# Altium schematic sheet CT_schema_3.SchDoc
size 276 x 169 mm
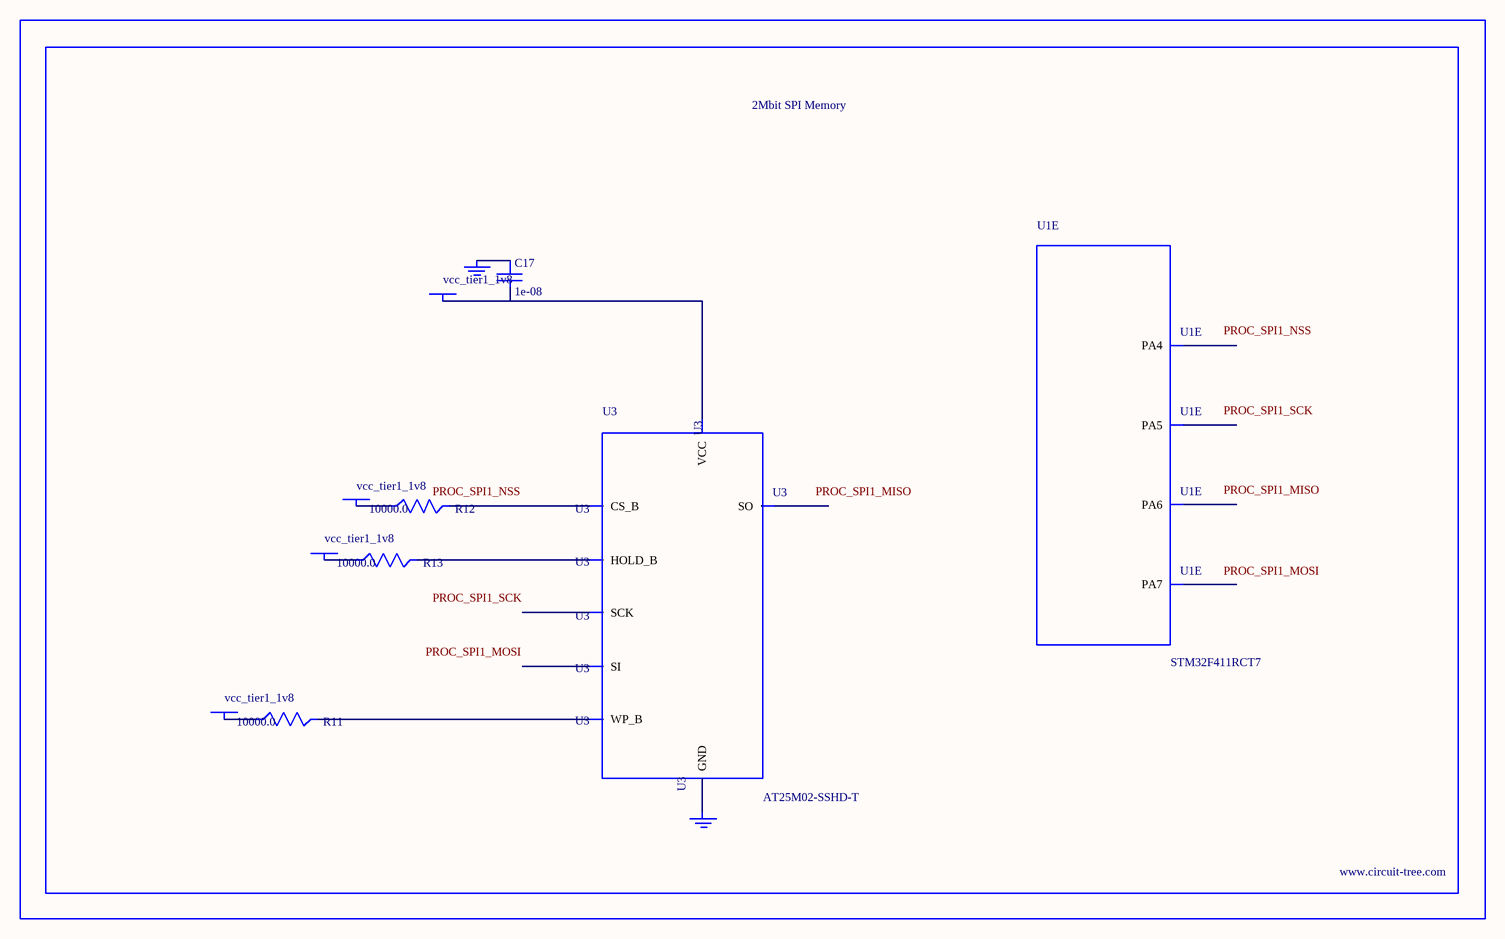
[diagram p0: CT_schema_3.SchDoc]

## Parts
BORDER2  (no value)
C17  1e-08  [C0402]
GND_INSTANCE_2_0  (no value)
GND_INSTANCE_2_1  (no value)
POWER_INSTANCE_2_0  vcc_tier1_1v8
POWER_INSTANCE_2_1  vcc_tier1_1v8
POWER_INSTANCE_2_2  vcc_tier1_1v8
POWER_INSTANCE_2_3  vcc_tier1_1v8
R11  10000.0  [R0603]
R12  10000.0  [R0603]
R13  10000.0  [R0603]
U1  STM32F411RCT7  [LQFP64]  (part E of 8)
U3  AT25M02-SSHD-T  [SOIC-8]

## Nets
NetC17_1: C17.1 GND_INSTANCE_2_0.0(GND)
NetC17_2: C17.2 POWER_INSTANCE_2_3.0(PWR) U3.8(VCC)
NetGND_INSTANCE_2_1_0: GND_INSTANCE_2_1.0(GND) U3.4(GND)
NetPOWER_INSTANCE_2_0_0: POWER_INSTANCE_2_0.0(PWR) R12.1
NetPOWER_INSTANCE_2_1_0: POWER_INSTANCE_2_1.0(PWR) R11.1
NetPOWER_INSTANCE_2_2_0: POWER_INSTANCE_2_2.0(PWR) R13.1
NetR11_2: R11.2 U3.3(WP_B)
NetR12_2: R12.2 U3.1(CS_B)
NetR13_2: R13.2 U3.7(HOLD_B)

Not connected (* = marked no-connect by the designer): U1 20(PA4) 21(PA5) 22(PA6) 23(PA7); U3 2(SO) 5(SI) 6(SCK)

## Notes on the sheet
- Labels drawn without touching a wire or pin: PROC_SPI1_MISO, PROC_SPI1_MOSI, PROC_SPI1_NSS, PROC_SPI1_SCK

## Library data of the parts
BORDER2 = BORDER_PAGE2
C17 = C0402C103K3RAC
GND_INSTANCE_2_0 GND_INSTANCE_2_1 = GND
POWER_INSTANCE_2_0-POWER_INSTANCE_2_3 = PWR
R11-R13 = RC0603JR-0710KL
